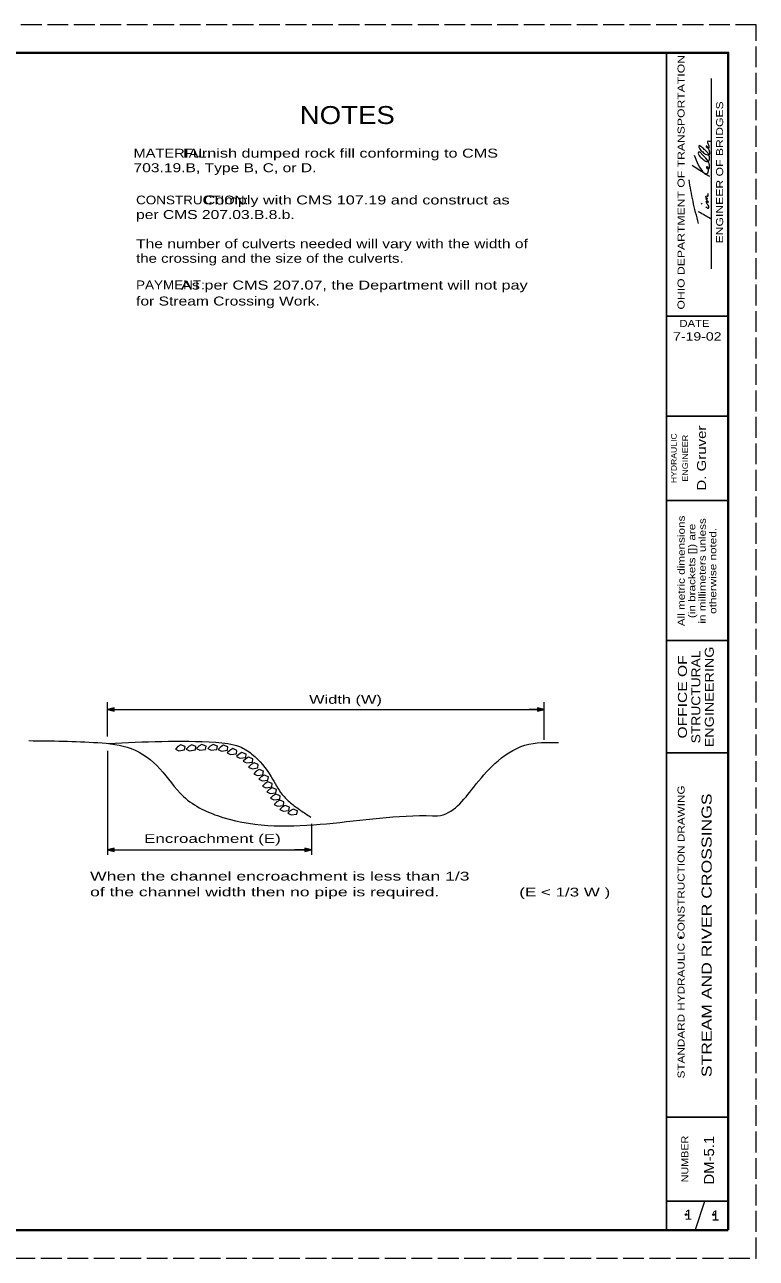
# Model space of a CAD drawing. Extents: x 1083.1 to 1117.1, y 719.4 to 741.4.
# Drawn here: x 1104.08 to 1117.13, y 719.35 to 741.35 of the extents above; entities that cross this region are included whole.
import ezdxf
from ezdxf.enums import TextEntityAlignment as Align

# ---------------------------------------------------------------- set-up
doc = ezdxf.new("R2010")
doc.units = 0
doc.header["$LTSCALE"] = 0.062
doc.header["$PDMODE"] = 32
doc.header["$PDSIZE"] = 0.031
doc.linetypes.add('LONG_DASHED', pattern=[7.5, 6, -1.5])
doc.layers.add('1', color=7, linetype='Continuous', lineweight=13)

msp = doc.modelspace()

# ---------------------------------------------------------------- hatches: boundary and pattern name
at = {"layer": '1'}
for points in [[(1105.67383, 729.16942), (1105.55633, 729.14), (1105.67383, 729.11058)], [(1113.22333, 729.11058), (1113.34083, 729.14), (1113.22333, 729.16942)], [(1105.67383, 726.66842), (1105.55633, 726.639), (1105.67383, 726.60958)], [(1109.07658, 726.60958), (1109.19408, 726.639), (1109.07658, 726.66842)]]:
    msp.add_hatch(color=256, dxfattribs=at).paths.add_polyline_path(points)

# ---------------------------------------------------------------- linework, layer by layer
at = {"layer": '1', "lineweight": 25}
for p, q in [((1085.12642, 740.85408), (1116.62642, 740.85408)), ((1115.52642, 719.871), (1115.52642, 740.871)), ((1116.62642, 740.871), (1116.62642, 719.871)), ((1116.62642, 736.15517), (1115.52642, 736.15517)), ((1116.62642, 734.371), (1115.52642, 734.371)), ((1116.62642, 732.871), (1115.52642, 732.871)), ((1116.62642, 730.371), (1115.52642, 730.371)), ((1116.62642, 728.371), (1115.52642, 728.371)), ((1116.62642, 721.871), (1115.52642, 721.871)), ((1116.62642, 720.371), (1115.52642, 720.371))]:
    msp.add_line(p, q, dxfattribs=at)
at = {"layer": '1', "lineweight": 40}
for p, q in [((1085.12642, 740.85408), (1116.62642, 740.85408)), ((1116.62642, 740.85983), (1116.62642, 719.85983))]:
    msp.add_line(p, q, dxfattribs=at)
at = {"layer": '1'}
for p, q in [((1116.32517, 737.002), (1116.32517, 740.39208)), ((1116.15767, 738.15292), (1116.1475, 738.17217)), ((1105.55633, 728.6585), (1105.55633, 729.27475)), ((1105.55633, 729.14), (1113.34083, 729.14)), ((1105.55633, 729.14), (1105.925, 729.14)), ((1113.34083, 729.14), (1113.07592, 729.14)), ((1113.34083, 728.60083), (1113.34083, 729.27475)), ((1105.55633, 728.40617), (1105.55633, 726.54917)), ((1109.19408, 727.10325), (1109.19408, 726.54917)), ((1105.55633, 726.639), (1109.19408, 726.639)), ((1105.55633, 726.639), (1105.89833, 726.639)), ((1109.19408, 726.639), (1108.88825, 726.639)), ((1116.04308, 719.871), (1116.20975, 720.371))]:
    msp.add_line(p, q, dxfattribs=at)
at = {"layer": '1', "linetype": 'LONG_DASHED'}
msp.add_lwpolyline([(1083.12642, 719.35408), (1117.12642, 719.35408), (1117.12642, 741.35408), (1083.12642, 741.35408)], close=True, dxfattribs=at)
at = {"layer": '1', "lineweight": 25}
msp.add_lwpolyline([(1116.62642, 719.85408), (1085.12642, 719.85408), (1085.12642, 740.85408)], dxfattribs=at)
at = {"layer": '1', "lineweight": 40}
for points in [[(1116.62642, 719.85408), (1085.12642, 719.85408), (1085.12642, 740.85408), (1116.62642, 740.85408)], [(1116.62642, 719.85408), (1085.12642, 719.85408), (1085.12642, 740.85408)]]:
    msp.add_lwpolyline(points, dxfattribs=at)
at = {"layer": '1'}
for points in [[(1105.67383, 729.16942), (1105.55633, 729.14), (1105.67383, 729.11058)], [(1113.22333, 729.11058), (1113.34083, 729.14), (1113.22333, 729.16942)], [(1106.8625, 728.51058), (1106.81008, 728.48058), (1106.76517, 728.43567), (1106.825, 728.40575), (1106.92983, 728.42075), (1106.93733, 728.48058)], [(1107.05717, 728.51058), (1107.00475, 728.48058), (1106.95983, 728.43567), (1107.01967, 728.40575), (1107.1245, 728.42075), (1107.132, 728.48058)], [(1107.23675, 728.51808), (1107.18433, 728.48808), (1107.13942, 728.44317), (1107.19925, 728.41325), (1107.30408, 728.42825), (1107.31158, 728.48808)], [(1107.43883, 728.51808), (1107.38642, 728.48808), (1107.3415, 728.44317), (1107.40133, 728.41325), (1107.50617, 728.42825), (1107.51367, 728.48808)], [(1107.626, 728.50317), (1107.57358, 728.47317), (1107.52867, 728.42825), (1107.5885, 728.39833), (1107.69333, 728.41333), (1107.70083, 728.47317)], [(1107.78775, 728.44317), (1107.73533, 728.41317), (1107.69042, 728.36825), (1107.75025, 728.33833), (1107.85508, 728.35333), (1107.86258, 728.41317)], [(1107.95242, 728.37575), (1107.9, 728.34575), (1107.85508, 728.30083), (1107.91492, 728.27092), (1108.01975, 728.28592), (1108.02725, 728.34575)], [(1108.07217, 728.29342), (1108.01975, 728.26342), (1107.97483, 728.2185), (1108.03467, 728.18858), (1108.1395, 728.20358), (1108.147, 728.26342)], [(1108.1695, 728.18858), (1108.11708, 728.15858), (1108.07217, 728.11367), (1108.132, 728.08375), (1108.23683, 728.09875), (1108.24433, 728.15858)], [(1108.25933, 728.06875), (1108.20692, 728.03875), (1108.162, 727.99383), (1108.22183, 727.96392), (1108.32667, 727.97892), (1108.33417, 728.03875)], [(1108.34908, 727.97142), (1108.29667, 727.94142), (1108.25175, 727.8965), (1108.31158, 727.86658), (1108.41642, 727.88158), (1108.42392, 727.94142)], [(1108.4165, 727.85167), (1108.36408, 727.82167), (1108.31917, 727.77675), (1108.379, 727.74683), (1108.48383, 727.76183), (1108.49133, 727.82167)], [(1108.49133, 727.74683), (1108.43892, 727.71683), (1108.394, 727.67192), (1108.45383, 727.642), (1108.55867, 727.657), (1108.56617, 727.71683)], [(1108.55867, 727.6345), (1108.50625, 727.6045), (1108.46133, 727.55958), (1108.52117, 727.52967), (1108.626, 727.54467), (1108.6335, 727.6045)], [(1108.62608, 727.52217), (1108.57367, 727.49217), (1108.52875, 727.44725), (1108.58858, 727.41733), (1108.69342, 727.43233), (1108.70092, 727.49217)], [(1108.72342, 727.43233), (1108.671, 727.40233), (1108.62608, 727.35742), (1108.68592, 727.3275), (1108.79075, 727.3425), (1108.79825, 727.40233)], [(1108.86558, 727.36492), (1108.81317, 727.33492), (1108.76825, 727.29), (1108.82808, 727.26008), (1108.93292, 727.27508), (1108.94042, 727.33492)], [(1105.67383, 726.66842), (1105.55633, 726.639), (1105.67383, 726.60958)], [(1109.07658, 726.60958), (1109.19408, 726.639), (1109.07658, 726.66842)]]:
    msp.add_lwpolyline(points, close=True, dxfattribs=at)
for points in [[(1116.01825, 739.028), (1116.20142, 738.69967), (1116.21658, 738.68908), (1116.22675, 738.68908), (1116.25867, 738.71275), (1116.27375, 738.74692), (1116.26875, 738.79817), (1116.25183, 738.82), (1116.23833, 738.82), (1116.23658, 738.807), (1116.24675, 738.79183), (1116.26025, 738.78342), (1116.27533, 738.78342), (1116.2905, 738.805), (1116.29392, 738.82433), (1116.28367, 738.87967), (1116.20142, 739.00008), (1116.15592, 739.04475), (1116.119, 739.07933), (1116.09383, 739.0815), (1116.09558, 739.04292), (1116.12075, 739.00417), (1116.188, 738.94183), (1116.23008, 738.91642), (1116.26375, 738.91192), (1116.28708, 738.93792), (1116.29392, 738.97208), (1116.28883, 738.99783), (1116.25867, 739.071), (1116.22842, 739.103), (1116.16783, 739.15642), (1116.13917, 739.18225), (1116.10567, 739.1975), (1116.10225, 739.1695), (1116.11233, 739.14367), (1116.1695, 739.08375), (1116.24017, 739.0365), (1116.29217, 739.03883), (1116.2905, 739.0965), (1116.27867, 739.13942), (1116.26533, 739.16517), (1116.25517, 739.17592), (1116.23175, 739.19092), (1116.2335, 739.17383), (1116.26875, 739.15233), (1116.28367, 739.16308), (1116.27058, 739.21675), (1116.262, 739.24467), (1116.25867, 739.25733), (1116.25867, 739.27017), (1116.25867, 739.27883), (1116.28367, 739.27667), (1116.30908, 739.27667)], [(1115.97942, 738.84575), (1116.20317, 738.70825), (1116.28883, 738.65258)], [(1116.09567, 737.80875), (1115.997, 738.204), (1115.92575, 738.58633)], [(1116.22675, 738.10767), (1116.235, 738.097), (1116.27217, 738.08408), (1116.27692, 738.1165), (1116.25183, 738.15292), (1116.23658, 738.18917), (1116.23658, 738.20842), (1116.25183, 738.20217), (1116.262, 738.19133), (1116.27217, 738.187), (1116.2485, 738.21917), (1116.23658, 738.23417), (1116.2335, 738.2515), (1116.25692, 738.24492), (1116.2485, 738.25358), (1116.22333, 738.28142), (1116.2335, 738.29658), (1116.25025, 738.29858), (1116.25867, 738.29658), (1116.26875, 738.31792), (1116.262, 738.34583)], [(1116.31083, 737.89317), (1116.10567, 738.01317), (1116.09008, 738.02358)], [(1104.15025, 728.58625), (1105.38025, 728.55008), (1105.97908, 728.44525), (1106.488, 728.08583), (1106.90717, 727.59167), (1107.61075, 727.21725), (1111.35325, 727.24725), (1111.44308, 727.24725), (1112.08683, 727.75642), (1112.46108, 728.17575), (1113, 728.50517), (1113.59542, 728.55267)], [(1105.574, 728.53567), (1107.4875, 728.55592), (1107.90667, 728.48108), (1108.13125, 728.34625), (1108.47558, 727.94192), (1108.67017, 727.62742), (1108.81983, 727.47767), (1108.9995, 727.34292), (1109.17917, 727.22308)]]:
    msp.add_spline(points, degree=3, dxfattribs=at)
for p in [(1115.78383, 725.077), (1116.21667, 725.08433), (1115.8745, 720.13475), (1116.36292, 720.13375)]:
    msp.add_point(p, dxfattribs=at)

# ---------------------------------------------------------------- texts
for s, height, width, p in [('OHIO DEPARTMENT OF TRANSPORTATION', 0.125, 1.3, (1115.84633, 738.54325)), ('ENGINEER OF BRIDGES', 0.125, 1.3, (1116.53467, 738.72004)), ('D. Gruver', 0.16, 1.25, (1116.22917, 733.62517)), ('HYDRAULIC', 0.1, 1.15, (1115.7055, 733.62208)), ('ENGINEER', 0.1, 1.2, (1115.90642, 733.62212)), ('All metric dimensions', 0.125, 1.25, (1115.85025, 731.61308)), ('(in brackets []) are', 0.125, 1.25, (1116.03775, 731.61308)), ('in millimeters unless', 0.125, 1.25, (1116.22525, 731.61312)), ('otherwise noted.', 0.125, 1.25, (1116.41275, 731.61308)), ('STRUCTURAL', 0.16, 1.15, (1116.12817, 729.36546)), ('ENGINEERING', 0.16, 1.2, (1116.36817, 729.36554)), ('OFFICE OF', 0.16, 1.3, (1115.88817, 729.36546)), ('STANDARD HYDRAULIC CONSTRUCTION DRAWING', 0.125, 1.25, (1115.84633, 725.17504)), ('STREAM AND RIVER CROSSINGS', 0.18, 1.3, (1116.33017, 725.11421)), ('NUMBER', 0.125, 1.15, (1115.91342, 721.12508)), ('DM-5.1', 0.18, 1.1, (1116.37308, 721.10446))]:
    msp.add_text(s, height=height, rotation=90, dxfattribs=dict(at, width=width)).set_placement(p, align=Align.CENTER)
for s, height, width, p in [('NOTES', 0.32, 1.15, (1109.83121, 739.58258)), ('DATE', 0.125, 1.2, (1116.02312, 735.96375)), ('7-19-02', 0.15, 1.25, (1116.07346, 735.71933))]:
    msp.add_text(s, height=height, dxfattribs=dict(at, width=width)).set_placement(p, align=Align.CENTER)
for s, height, width, p in [('MATERIAL:', 0.156, 1.25, (1106.01858, 738.98508)), ('           Furnish dumped rock fill conforming to CMS ', 0.16, 1.35, (1106.01858, 738.98308)), ('703.19.B, Type B, C, or D.  ', 0.16, 1.3, (1106.01858, 738.72308)), ('CONSTRUCTION:', 0.156, 1.15, (1106.06425, 738.14992)), ('               Comply with CMS 107.19 and construct as ', 0.16, 1.35, (1106.06425, 738.14817)), ('per CMS 207.03.B.8.b.', 0.16, 1.3, (1106.06425, 737.88817)), ('The number of culverts needed will vary with the width of ', 0.16, 1.3, (1106.06425, 737.36817)), ('the crossing and the size of the culverts.', 0.16, 1.25, (1106.06425, 737.10817)), ('PAYMENT:', 0.156, 1.15, (1106.06425, 736.63608)), ('          As per CMS 207.07, the Department will not pay ', 0.16, 1.35, (1106.06425, 736.63067)), ('for Stream Crossing Work.', 0.16, 1.3, (1106.06425, 736.34567)), ('Width (W)', 0.156, 1.4, (1109.15083, 729.243)), ('Encroachment (E)', 0.156, 1.45, (1106.20775, 726.76217)), ('When the channel encroachment is less than 1/3', 0.156, 1.5, (1105.24442, 726.091)), ('of the channel width then no pipe is required.', 0.156, 1.5, (1105.24442, 725.81)), ('(E < 1/3 W )', 0.156, 1.45, (1112.89867, 725.80742))]:
    msp.add_text(s, height=height, dxfattribs=dict(at, width=width)).set_placement(p)
for p in [(1115.91427, 720.04108), (1116.3971, 720.0285)]:
    msp.add_text('1', height=0.18, dxfattribs=at).set_placement(p, align=Align.CENTER)

doc.saveas('drawing.dxf')
